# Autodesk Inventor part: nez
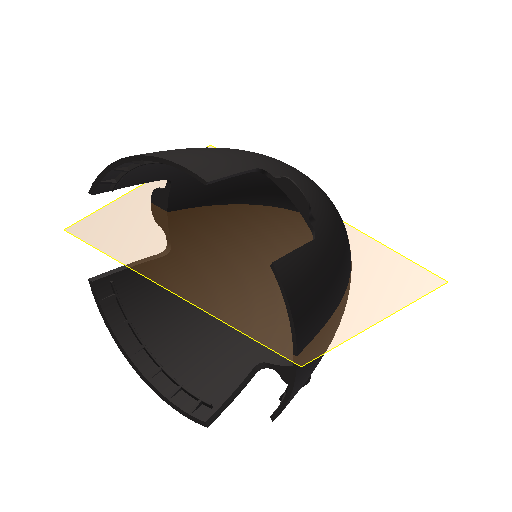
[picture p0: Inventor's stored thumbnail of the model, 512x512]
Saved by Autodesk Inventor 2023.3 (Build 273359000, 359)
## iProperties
Created: 2014-09
Part Number: nez
Material: Générique
Document SubType Name: Modeling
Designer: papa
Density: 1 g/cm^3
Appearance: Par défaut
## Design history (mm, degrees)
node "nez1"
node "nez"
node "Base1"
